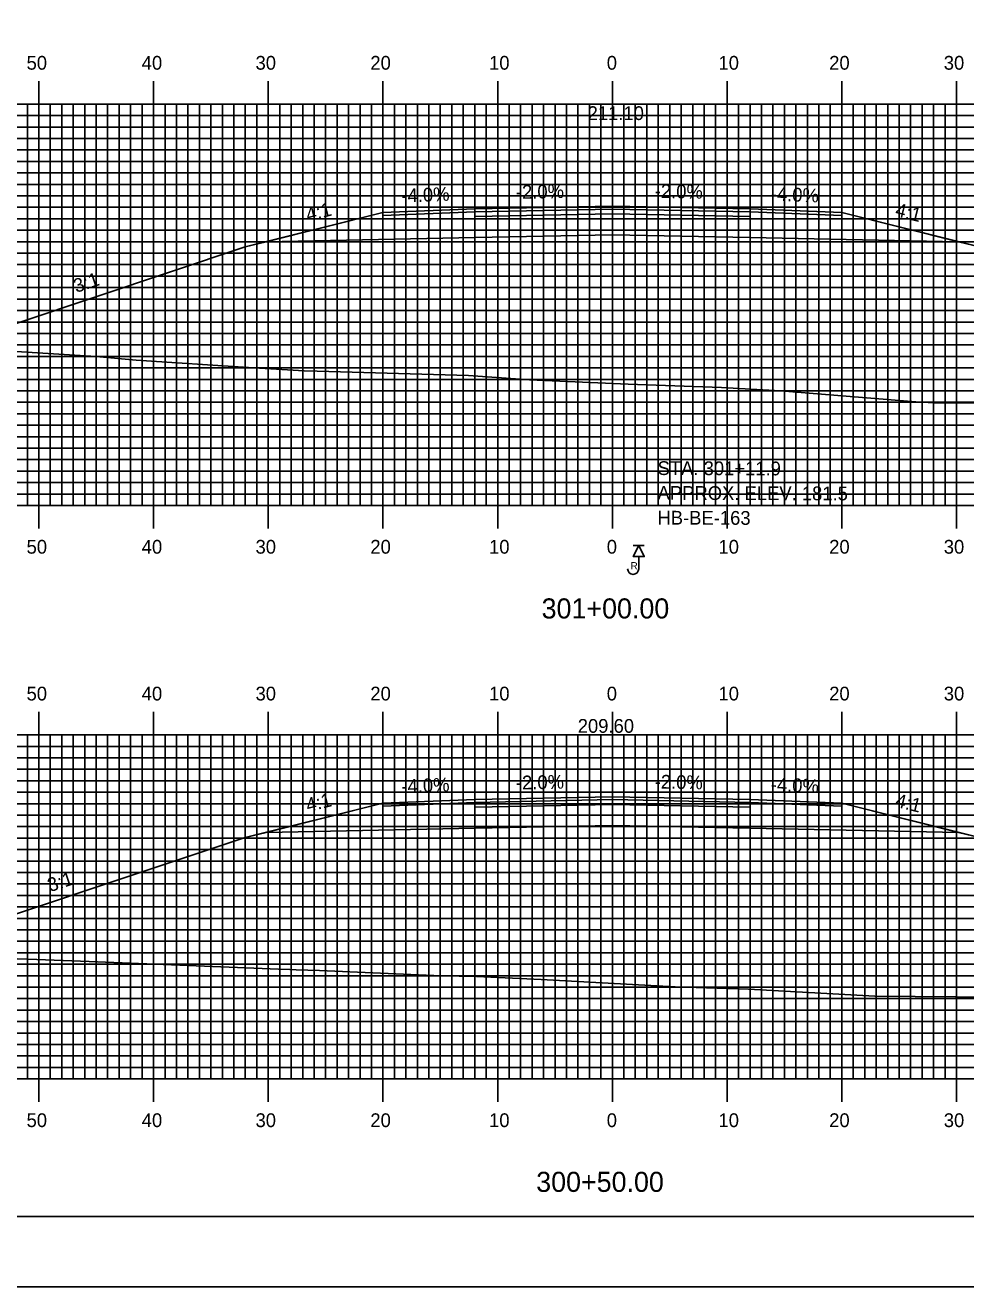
# Model space of a CAD drawing. Extents: x 1815702 to 1816046, y 442591 to 442811.
# Drawn here: x 1815816.9 to 1815898.9, y 442590.5 to 442700.5 of the extents above; entities that cross this region are included whole.
import ezdxf

# ---------------------------------------------------------------- set-up
doc = ezdxf.new("R2010")
doc.units = 0
for name, color, linetype in [('ANNOTATION', 7, 'Continuous'), ('BORDER', 7, 'Continuous'), ('BORING - REFUSAL', 7, 'Continuous'), ('D_Roadway_Centerline', 7, 'Continuous'), ('D_Roadway_Centerline_Text', 7, 'Continuous'), ('D_Roadway_Edge_Shoulder', 7, 'Continuous'), ('D_Roadway_Edge_TW', 7, 'Continuous'), ('D_Roadway_Pavement', 7, 'Continuous'), ('D_Roadway_SlopeLines', 7, 'Continuous'), ('D_Roadway_SubGrade', 7, 'Continuous'), ('H_V ANNOTATION', 7, 'Continuous'), ('MAJOR', 7, 'Continuous'), ('MINOR', 7, 'Continuous'), ('PLOT BOUNDARY', 7, 'Continuous'), ('S_Roadway_Centerline', 7, 'Continuous')]:
    doc.layers.add(name, color=color, linetype=linetype)

msp = doc.modelspace()

# ---------------------------------------------------------------- linework, layer by layer
at = {"layer": 'BORDER'}
msp.add_lwpolyline([(1815718.45, 442596.67), (1816038.45, 442596.67), (1816038.45, 442806.67), (1815718.45, 442806.67)], close=True, dxfattribs=at)
at = {"layer": 'BORING - REFUSAL'}
for p, q in [((1815870.83, 442655.17), (1815869.87, 442655.17)), ((1815870.35, 442654.21), (1815870.35, 442653.15))]:
    msp.add_line(p, q, dxfattribs=at)
msp.add_lwpolyline([(1815870.35, 442655.17), (1815870.83, 442654.21), (1815869.87, 442654.21)], close=True, dxfattribs=at)
msp.add_arc((1815869.86, 442653.15), 0.485, 180, 0, dxfattribs=at)
at = {"layer": 'D_Roadway_Centerline'}
for points in [[(1815809.89, 442672.49), (1815836.05, 442681.21), (1815837.87, 442681.67), (1815848.05, 442684.21), (1815856.05, 442684.53), (1815868.05, 442684.77), (1815880.05, 442684.53), (1815888.05, 442684.21), (1815898.22, 442681.67), (1815900.05, 442681.21), (1815945.68, 442666)], [(1815805.36, 442619.48), (1815836.05, 442629.71), (1815837.87, 442630.17), (1815848.05, 442632.71), (1815856.05, 442633.03), (1815868.05, 442633.27), (1815880.05, 442633.03), (1815888.05, 442632.71), (1815898.22, 442630.17), (1815900.05, 442629.71), (1815943, 442615.39)]]:
    msp.add_lwpolyline(points, dxfattribs=at)
at = {"layer": 'D_Roadway_Edge_Shoulder'}
for points in [[(1815856.05, 442684.53), (1815848.05, 442684.21), (1815848.05, 442683.96), (1815856.05, 442684.28)], [(1815880.05, 442684.53), (1815888.05, 442684.21), (1815888.05, 442683.96), (1815880.05, 442684.28)], [(1815856.05, 442633.03), (1815848.05, 442632.71), (1815848.05, 442632.46), (1815856.05, 442632.78)], [(1815880.05, 442633.03), (1815888.05, 442632.71), (1815888.05, 442632.46), (1815880.05, 442632.78)]]:
    msp.add_lwpolyline(points, close=True, dxfattribs=at)
at = {"layer": 'D_Roadway_Edge_TW'}
for points in [[(1815856.05, 442684.28), (1815856.05, 442684.53), (1815868.05, 442684.77), (1815880.05, 442684.53), (1815880.05, 442684.28), (1815868.05, 442684.52)], [(1815856.05, 442632.78), (1815856.05, 442633.03), (1815868.05, 442633.27), (1815880.05, 442633.03), (1815880.05, 442632.78), (1815868.05, 442633.02)]]:
    msp.add_lwpolyline(points, close=True, dxfattribs=at)
at = {"layer": 'D_Roadway_Pavement'}
for points in [[(1815856.05, 442683.86), (1815856.05, 442684.28), (1815868.05, 442684.52), (1815880.05, 442684.28), (1815880.05, 442683.86), (1815868.05, 442684.1)], [(1815856.05, 442632.36), (1815856.05, 442632.78), (1815868.05, 442633.02), (1815880.05, 442632.78), (1815880.05, 442632.36), (1815868.05, 442632.6)]]:
    msp.add_lwpolyline(points, close=True, dxfattribs=at)
at = {"layer": 'D_Roadway_SlopeLines'}
for points in [[(1815848.05, 442684.21), (1815836.05, 442681.21), (1815809.89, 442672.49)], [(1815888.05, 442684.21), (1815900.05, 442681.21), (1815945.68, 442666)], [(1815848.05, 442632.71), (1815836.05, 442629.71), (1815805.36, 442619.48)], [(1815888.05, 442632.71), (1815900.05, 442629.71), (1815943, 442615.39)]]:
    msp.add_lwpolyline(points, dxfattribs=at)
at = {"layer": 'D_Roadway_SubGrade'}
for points in [[(1815856.05, 442682.03), (1815837.87, 442681.67), (1815848.05, 442684.21), (1815848.05, 442683.96), (1815856.05, 442684.28), (1815868.05, 442684.52), (1815880.05, 442684.28), (1815888.05, 442683.96), (1815888.05, 442684.21), (1815898.22, 442681.67), (1815880.05, 442682.03), (1815868.05, 442682.27)], [(1815856.05, 442630.53), (1815837.87, 442630.17), (1815848.05, 442632.71), (1815848.05, 442632.46), (1815856.05, 442632.78), (1815868.05, 442633.02), (1815880.05, 442632.78), (1815888.05, 442632.46), (1815888.05, 442632.71), (1815898.22, 442630.17), (1815880.05, 442630.53), (1815868.05, 442630.77)]]:
    msp.add_lwpolyline(points, close=True, dxfattribs=at)
at = {"layer": 'MAJOR'}
for p, q in [((1815818.05, 442695.67), (1815818.05, 442693.67)), ((1815828.05, 442695.67), (1815828.05, 442693.67)), ((1815838.05, 442695.67), (1815838.05, 442693.67)), ((1815848.05, 442695.67), (1815848.05, 442693.67)), ((1815858.05, 442695.67), (1815858.05, 442693.67)), ((1815868.05, 442695.67), (1815868.05, 442693.67)), ((1815878.05, 442695.67), (1815878.05, 442693.67)), ((1815888.05, 442695.67), (1815888.05, 442693.67)), ((1815898.05, 442695.67), (1815898.05, 442693.67)), ((1815728.05, 442693.67), (1816008.05, 442693.67)), ((1815728.05, 442693.67), (1816008.05, 442693.67)), ((1815818.05, 442658.67), (1815818.05, 442693.67)), ((1815828.05, 442658.67), (1815828.05, 442693.67)), ((1815838.05, 442658.67), (1815838.05, 442693.67)), ((1815848.05, 442658.67), (1815848.05, 442693.67)), ((1815858.05, 442658.67), (1815858.05, 442693.67)), ((1815868.05, 442658.67), (1815868.05, 442693.67)), ((1815878.05, 442658.67), (1815878.05, 442693.67)), ((1815888.05, 442658.67), (1815888.05, 442693.67)), ((1815898.05, 442658.67), (1815898.05, 442693.67)), ((1815728.05, 442688.67), (1816008.05, 442688.67)), ((1815728.05, 442683.67), (1816008.05, 442683.67)), ((1815728.05, 442678.67), (1816008.05, 442678.67)), ((1815728.05, 442673.67), (1816008.05, 442673.67)), ((1815728.05, 442668.67), (1816008.05, 442668.67)), ((1815728.05, 442663.67), (1816008.05, 442663.67)), ((1815728.05, 442658.67), (1816008.05, 442658.67)), ((1815728.05, 442658.67), (1816008.05, 442658.67)), ((1815818.05, 442656.66), (1815818.05, 442658.67)), ((1815828.05, 442656.66), (1815828.05, 442658.67)), ((1815838.05, 442656.66), (1815838.05, 442658.67)), ((1815848.05, 442656.66), (1815848.05, 442658.67)), ((1815858.05, 442656.66), (1815858.05, 442658.67)), ((1815868.05, 442656.66), (1815868.05, 442658.67)), ((1815878.05, 442656.66), (1815878.05, 442658.67)), ((1815888.05, 442656.66), (1815888.05, 442658.67)), ((1815898.05, 442656.66), (1815898.05, 442658.67)), ((1815818.05, 442640.67), (1815818.05, 442638.67)), ((1815828.05, 442640.67), (1815828.05, 442638.67)), ((1815838.05, 442640.67), (1815838.05, 442638.67)), ((1815848.05, 442640.67), (1815848.05, 442638.67)), ((1815858.05, 442640.67), (1815858.05, 442638.67)), ((1815868.05, 442640.67), (1815868.05, 442638.67)), ((1815878.05, 442640.67), (1815878.05, 442638.67)), ((1815888.05, 442640.67), (1815888.05, 442638.67)), ((1815898.05, 442640.67), (1815898.05, 442638.67)), ((1815728.05, 442638.67), (1816008.05, 442638.67)), ((1815728.05, 442638.67), (1816008.05, 442638.67)), ((1815818.05, 442608.67), (1815818.05, 442638.67)), ((1815828.05, 442608.67), (1815828.05, 442638.67)), ((1815838.05, 442608.67), (1815838.05, 442638.67)), ((1815848.05, 442608.67), (1815848.05, 442638.67)), ((1815858.05, 442608.67), (1815858.05, 442638.67)), ((1815868.05, 442608.67), (1815868.05, 442638.67)), ((1815878.05, 442608.67), (1815878.05, 442638.67)), ((1815888.05, 442608.67), (1815888.05, 442638.67)), ((1815898.05, 442608.67), (1815898.05, 442638.67)), ((1815728.05, 442633.67), (1816008.05, 442633.67)), ((1815728.05, 442628.67), (1816008.05, 442628.67)), ((1815728.05, 442623.67), (1816008.05, 442623.67)), ((1815728.05, 442618.67), (1816008.05, 442618.67)), ((1815728.05, 442613.67), (1816008.05, 442613.67)), ((1815728.05, 442608.67), (1816008.05, 442608.67)), ((1815728.05, 442608.67), (1816008.05, 442608.67)), ((1815818.05, 442606.66), (1815818.05, 442608.67)), ((1815828.05, 442606.66), (1815828.05, 442608.67)), ((1815838.05, 442606.66), (1815838.05, 442608.67)), ((1815848.05, 442606.66), (1815848.05, 442608.67)), ((1815858.05, 442606.66), (1815858.05, 442608.67)), ((1815868.05, 442606.66), (1815868.05, 442608.67)), ((1815878.05, 442606.66), (1815878.05, 442608.67)), ((1815888.05, 442606.66), (1815888.05, 442608.67)), ((1815898.05, 442606.66), (1815898.05, 442608.67))]:
    msp.add_line(p, q, dxfattribs=at)
at = {"layer": 'MINOR'}
for p, q in [((1815817.05, 442658.67), (1815817.05, 442693.67)), ((1815819.05, 442658.67), (1815819.05, 442693.67)), ((1815820.05, 442658.67), (1815820.05, 442693.67)), ((1815821.05, 442658.67), (1815821.05, 442693.67)), ((1815822.05, 442658.67), (1815822.05, 442693.67)), ((1815823.05, 442658.67), (1815823.05, 442693.67)), ((1815824.05, 442658.67), (1815824.05, 442693.67)), ((1815825.05, 442658.67), (1815825.05, 442693.67)), ((1815826.05, 442658.67), (1815826.05, 442693.67)), ((1815827.05, 442658.67), (1815827.05, 442693.67)), ((1815829.05, 442658.67), (1815829.05, 442693.67)), ((1815830.05, 442658.67), (1815830.05, 442693.67)), ((1815831.05, 442658.67), (1815831.05, 442693.67)), ((1815832.05, 442658.67), (1815832.05, 442693.67)), ((1815833.05, 442658.67), (1815833.05, 442693.67)), ((1815834.05, 442658.67), (1815834.05, 442693.67)), ((1815835.05, 442658.67), (1815835.05, 442693.67)), ((1815836.05, 442658.67), (1815836.05, 442693.67)), ((1815837.05, 442658.67), (1815837.05, 442693.67)), ((1815839.05, 442658.67), (1815839.05, 442693.67)), ((1815840.05, 442658.67), (1815840.05, 442693.67)), ((1815841.05, 442658.67), (1815841.05, 442693.67)), ((1815842.05, 442658.67), (1815842.05, 442693.67)), ((1815843.05, 442658.67), (1815843.05, 442693.67)), ((1815844.05, 442658.67), (1815844.05, 442693.67)), ((1815845.05, 442658.67), (1815845.05, 442693.67)), ((1815846.05, 442658.67), (1815846.05, 442693.67)), ((1815847.05, 442658.67), (1815847.05, 442693.67)), ((1815849.05, 442658.67), (1815849.05, 442693.67)), ((1815850.05, 442658.67), (1815850.05, 442693.67)), ((1815851.05, 442658.67), (1815851.05, 442693.67)), ((1815852.05, 442658.67), (1815852.05, 442693.67)), ((1815853.05, 442658.67), (1815853.05, 442693.67)), ((1815854.05, 442658.67), (1815854.05, 442693.67)), ((1815855.05, 442658.67), (1815855.05, 442693.67)), ((1815856.05, 442658.67), (1815856.05, 442693.67)), ((1815857.05, 442658.67), (1815857.05, 442693.67)), ((1815859.05, 442658.67), (1815859.05, 442693.67)), ((1815860.05, 442658.67), (1815860.05, 442693.67)), ((1815861.05, 442658.67), (1815861.05, 442693.67)), ((1815862.05, 442658.67), (1815862.05, 442693.67)), ((1815863.05, 442658.67), (1815863.05, 442693.67)), ((1815864.05, 442658.67), (1815864.05, 442693.67)), ((1815865.05, 442658.67), (1815865.05, 442693.67)), ((1815866.05, 442658.67), (1815866.05, 442693.67)), ((1815867.05, 442658.67), (1815867.05, 442693.67)), ((1815869.05, 442658.67), (1815869.05, 442693.67)), ((1815870.05, 442658.67), (1815870.05, 442693.67)), ((1815871.05, 442658.67), (1815871.05, 442693.67)), ((1815872.05, 442658.67), (1815872.05, 442693.67)), ((1815873.05, 442658.67), (1815873.05, 442693.67)), ((1815874.05, 442658.67), (1815874.05, 442693.67)), ((1815875.05, 442658.67), (1815875.05, 442693.67)), ((1815876.05, 442658.67), (1815876.05, 442693.67)), ((1815877.05, 442658.67), (1815877.05, 442693.67)), ((1815879.05, 442658.67), (1815879.05, 442693.67)), ((1815880.05, 442658.67), (1815880.05, 442693.67)), ((1815881.05, 442658.67), (1815881.05, 442693.67)), ((1815882.05, 442658.67), (1815882.05, 442693.67)), ((1815883.05, 442658.67), (1815883.05, 442693.67)), ((1815884.05, 442658.67), (1815884.05, 442693.67)), ((1815885.05, 442658.67), (1815885.05, 442693.67)), ((1815886.05, 442658.67), (1815886.05, 442693.67)), ((1815887.05, 442658.67), (1815887.05, 442693.67)), ((1815889.05, 442658.67), (1815889.05, 442693.67)), ((1815890.05, 442658.67), (1815890.05, 442693.67)), ((1815891.05, 442658.67), (1815891.05, 442693.67)), ((1815892.05, 442658.67), (1815892.05, 442693.67)), ((1815893.05, 442658.67), (1815893.05, 442693.67)), ((1815894.05, 442658.67), (1815894.05, 442693.67)), ((1815895.05, 442658.67), (1815895.05, 442693.67)), ((1815896.05, 442658.67), (1815896.05, 442693.67)), ((1815897.05, 442658.67), (1815897.05, 442693.67)), ((1815728.05, 442692.67), (1816008.05, 442692.67)), ((1815728.05, 442691.67), (1816008.05, 442691.67)), ((1815728.05, 442690.67), (1816008.05, 442690.67)), ((1815728.05, 442689.67), (1816008.05, 442689.67)), ((1815728.05, 442687.67), (1816008.05, 442687.67)), ((1815728.05, 442686.67), (1816008.05, 442686.67)), ((1815728.05, 442685.67), (1816008.05, 442685.67)), ((1815728.05, 442684.67), (1816008.05, 442684.67)), ((1815728.05, 442682.67), (1816008.05, 442682.67)), ((1815728.05, 442681.67), (1816008.05, 442681.67)), ((1815728.05, 442680.67), (1816008.05, 442680.67)), ((1815728.05, 442679.67), (1816008.05, 442679.67)), ((1815728.05, 442677.67), (1816008.05, 442677.67)), ((1815728.05, 442676.67), (1816008.05, 442676.67)), ((1815728.05, 442675.67), (1816008.05, 442675.67)), ((1815728.05, 442674.67), (1816008.05, 442674.67)), ((1815728.05, 442672.67), (1816008.05, 442672.67)), ((1815728.05, 442671.67), (1816008.05, 442671.67)), ((1815728.05, 442670.67), (1816008.05, 442670.67)), ((1815728.05, 442669.67), (1816008.05, 442669.67)), ((1815728.05, 442667.67), (1816008.05, 442667.67)), ((1815728.05, 442666.67), (1816008.05, 442666.67)), ((1815728.05, 442665.67), (1816008.05, 442665.67)), ((1815728.05, 442664.67), (1816008.05, 442664.67)), ((1815728.05, 442662.67), (1816008.05, 442662.67)), ((1815728.05, 442661.67), (1816008.05, 442661.67)), ((1815728.05, 442660.67), (1816008.05, 442660.67)), ((1815728.05, 442659.67), (1816008.05, 442659.67)), ((1815817.05, 442608.67), (1815817.05, 442638.67)), ((1815819.05, 442608.67), (1815819.05, 442638.67)), ((1815820.05, 442608.67), (1815820.05, 442638.67)), ((1815821.05, 442608.67), (1815821.05, 442638.67)), ((1815822.05, 442608.67), (1815822.05, 442638.67)), ((1815823.05, 442608.67), (1815823.05, 442638.67)), ((1815824.05, 442608.67), (1815824.05, 442638.67)), ((1815825.05, 442608.67), (1815825.05, 442638.67)), ((1815826.05, 442608.67), (1815826.05, 442638.67)), ((1815827.05, 442608.67), (1815827.05, 442638.67)), ((1815829.05, 442608.67), (1815829.05, 442638.67)), ((1815830.05, 442608.67), (1815830.05, 442638.67)), ((1815831.05, 442608.67), (1815831.05, 442638.67)), ((1815832.05, 442608.67), (1815832.05, 442638.67)), ((1815833.05, 442608.67), (1815833.05, 442638.67)), ((1815834.05, 442608.67), (1815834.05, 442638.67)), ((1815835.05, 442608.67), (1815835.05, 442638.67)), ((1815836.05, 442608.67), (1815836.05, 442638.67)), ((1815837.05, 442608.67), (1815837.05, 442638.67)), ((1815839.05, 442608.67), (1815839.05, 442638.67)), ((1815840.05, 442608.67), (1815840.05, 442638.67)), ((1815841.05, 442608.67), (1815841.05, 442638.67)), ((1815842.05, 442608.67), (1815842.05, 442638.67)), ((1815843.05, 442608.67), (1815843.05, 442638.67)), ((1815844.05, 442608.67), (1815844.05, 442638.67)), ((1815845.05, 442608.67), (1815845.05, 442638.67)), ((1815846.05, 442608.67), (1815846.05, 442638.67)), ((1815847.05, 442608.67), (1815847.05, 442638.67)), ((1815849.05, 442608.67), (1815849.05, 442638.67)), ((1815850.05, 442608.67), (1815850.05, 442638.67)), ((1815851.05, 442608.67), (1815851.05, 442638.67)), ((1815852.05, 442608.67), (1815852.05, 442638.67)), ((1815853.05, 442608.67), (1815853.05, 442638.67)), ((1815854.05, 442608.67), (1815854.05, 442638.67)), ((1815855.05, 442608.67), (1815855.05, 442638.67)), ((1815856.05, 442608.67), (1815856.05, 442638.67)), ((1815857.05, 442608.67), (1815857.05, 442638.67)), ((1815859.05, 442608.67), (1815859.05, 442638.67)), ((1815860.05, 442608.67), (1815860.05, 442638.67)), ((1815861.05, 442608.67), (1815861.05, 442638.67)), ((1815862.05, 442608.67), (1815862.05, 442638.67)), ((1815863.05, 442608.67), (1815863.05, 442638.67)), ((1815864.05, 442608.67), (1815864.05, 442638.67)), ((1815865.05, 442608.67), (1815865.05, 442638.67)), ((1815866.05, 442608.67), (1815866.05, 442638.67)), ((1815867.05, 442608.67), (1815867.05, 442638.67)), ((1815869.05, 442608.67), (1815869.05, 442638.67)), ((1815870.05, 442608.67), (1815870.05, 442638.67)), ((1815871.05, 442608.67), (1815871.05, 442638.67)), ((1815872.05, 442608.67), (1815872.05, 442638.67)), ((1815873.05, 442608.67), (1815873.05, 442638.67)), ((1815874.05, 442608.67), (1815874.05, 442638.67)), ((1815875.05, 442608.67), (1815875.05, 442638.67)), ((1815876.05, 442608.67), (1815876.05, 442638.67)), ((1815877.05, 442608.67), (1815877.05, 442638.67)), ((1815879.05, 442608.67), (1815879.05, 442638.67)), ((1815880.05, 442608.67), (1815880.05, 442638.67)), ((1815881.05, 442608.67), (1815881.05, 442638.67)), ((1815882.05, 442608.67), (1815882.05, 442638.67)), ((1815883.05, 442608.67), (1815883.05, 442638.67)), ((1815884.05, 442608.67), (1815884.05, 442638.67)), ((1815885.05, 442608.67), (1815885.05, 442638.67)), ((1815886.05, 442608.67), (1815886.05, 442638.67)), ((1815887.05, 442608.67), (1815887.05, 442638.67)), ((1815889.05, 442608.67), (1815889.05, 442638.67)), ((1815890.05, 442608.67), (1815890.05, 442638.67)), ((1815891.05, 442608.67), (1815891.05, 442638.67)), ((1815892.05, 442608.67), (1815892.05, 442638.67)), ((1815893.05, 442608.67), (1815893.05, 442638.67)), ((1815894.05, 442608.67), (1815894.05, 442638.67)), ((1815895.05, 442608.67), (1815895.05, 442638.67)), ((1815896.05, 442608.67), (1815896.05, 442638.67)), ((1815897.05, 442608.67), (1815897.05, 442638.67)), ((1815728.05, 442637.67), (1816008.05, 442637.67)), ((1815728.05, 442636.67), (1816008.05, 442636.67)), ((1815728.05, 442635.67), (1816008.05, 442635.67)), ((1815728.05, 442634.67), (1816008.05, 442634.67)), ((1815728.05, 442632.67), (1816008.05, 442632.67)), ((1815728.05, 442631.67), (1816008.05, 442631.67)), ((1815728.05, 442630.67), (1816008.05, 442630.67)), ((1815728.05, 442629.67), (1816008.05, 442629.67)), ((1815728.05, 442627.67), (1816008.05, 442627.67)), ((1815728.05, 442626.67), (1816008.05, 442626.67)), ((1815728.05, 442625.67), (1816008.05, 442625.67)), ((1815728.05, 442624.67), (1816008.05, 442624.67)), ((1815728.05, 442622.67), (1816008.05, 442622.67)), ((1815728.05, 442621.67), (1816008.05, 442621.67)), ((1815728.05, 442620.67), (1816008.05, 442620.67)), ((1815728.05, 442619.67), (1816008.05, 442619.67)), ((1815728.05, 442617.67), (1816008.05, 442617.67)), ((1815728.05, 442616.67), (1816008.05, 442616.67)), ((1815728.05, 442615.67), (1816008.05, 442615.67)), ((1815728.05, 442614.67), (1816008.05, 442614.67)), ((1815728.05, 442612.67), (1816008.05, 442612.67)), ((1815728.05, 442611.67), (1816008.05, 442611.67)), ((1815728.05, 442610.67), (1816008.05, 442610.67)), ((1815728.05, 442609.67), (1816008.05, 442609.67))]:
    msp.add_line(p, q, dxfattribs=at)
at = {"layer": 'PLOT BOUNDARY'}
msp.add_lwpolyline([(1815702.26, 442590.55), (1816042.26, 442590.55), (1816042.26, 442810.55), (1815702.26, 442810.55)], close=True, dxfattribs=at)
at = {"layer": 'S_Roadway_Centerline'}
for points in [[(1815809.56, 442672.51), (1815823.05, 442671.65), (1815826.54, 442671.35), (1815836.32, 442670.69), (1815841.18, 442670.41), (1815842.31, 442670.37), (1815855.5, 442670.01), (1815860.83, 442669.64), (1815869.42, 442669.24), (1815877.56, 442668.97), (1815882.7, 442668.66), (1815894.49, 442667.72), (1815896.09, 442667.63), (1815900.12, 442667.6), (1815912.51, 442667.31), (1815923.93, 442666.7), (1815928.95, 442666.66), (1815937.45, 442666.3), (1815948.91, 442665.88), (1815962.14, 442665.79), (1815970.07, 442665.5), (1815986.57, 442665.4), (1816007.47, 442665.13), (1816008.05, 442665.13)], [(1815805.51, 442619.47), (1815817.11, 442619.1), (1815822.45, 442618.9), (1815838.94, 442618.25), (1815839.92, 442618.22), (1815840.49, 442618.19), (1815842.51, 442618.11), (1815853.16, 442617.67), (1815856.2, 442617.59), (1815861.83, 442617.35), (1815873.52, 442616.69), (1815879.92, 442616.49), (1815890.93, 442615.88), (1815904.99, 442615.76), (1815907.15, 442615.75), (1815907.54, 442615.75), (1815908.18, 442615.73), (1815924.18, 442615.54), (1815931.51, 442615.58), (1815941.78, 442615.41), (1815966.62, 442615.08)]]:
    msp.add_lwpolyline(points, dxfattribs=at)

# ---------------------------------------------------------------- texts
at = {"layer": 'ANNOTATION'}
for s, rotation, p in [('-4.0%', 2.2906, (1815849.68, 442685.08)), ('-2.0%', 1.1458, (1815859.65, 442685.4)), ('-2.0%', 358.8542, (1815871.73, 442685.5)), ('-4.0%', 357.7094, (1815881.84, 442685.26)), ('4:1', 14.0362, (1815841.5, 442683.43)), ('4:1', 345.9638, (1815892.64, 442683.92)), ('3:1', 18.4348, (1815821.31, 442677.2)), ('-4.0%', 2.2906, (1815849.68, 442633.58)), ('-2.0%', 1.1458, (1815859.65, 442633.9)), ('-2.0%', 358.8542, (1815871.73, 442634)), ('-4.0%', 357.7094, (1815881.84, 442633.76)), ('4:1', 14.0362, (1815841.5, 442631.93)), ('4:1', 345.9638, (1815892.64, 442632.42)), ('3:1', 18.4348, (1815819.04, 442624.95))]:
    msp.add_text(s, height=1.2, rotation=rotation, dxfattribs=at).set_placement(p)
at = {"layer": 'BORING - REFUSAL'}
for s, p in [('STA. 301+11.9', (1815871.99, 442661.33)), ('APPROX. ELEV. 181.5', (1815871.99, 442659.17)), ('HB-BE-163', (1815871.98, 442657.01))]:
    msp.add_text(s, height=1.2, rotation=359.8142, dxfattribs=at).set_placement(p)
msp.add_text('R', height=0.64, dxfattribs=at).set_placement((1815869.64, 442653.09))
at = {"layer": 'D_Roadway_Centerline'}
for s, p in [('C', (1815868.04, 442684.77)), ('L', (1815868.05, 442684.76)), ('C', (1815868.04, 442633.27)), ('L', (1815868.05, 442633.26))]:
    msp.add_text(s, height=0.0146, dxfattribs=at).set_placement(p)
at = {"layer": 'D_Roadway_Centerline_Text'}
for s, p in [('211.10', (1815865.89, 442692.28)), ('209.60', (1815865.03, 442638.85))]:
    msp.add_text(s, height=1.2, dxfattribs=at).set_placement(p)
at = {"layer": 'H_V ANNOTATION'}
for s, height, p in [('50', 1.2, (1815816.98, 442696.67)), ('40', 1.2, (1815827.02, 442696.67)), ('30', 1.2, (1815836.94, 442696.67)), ('20', 1.2, (1815846.95, 442696.67)), ('10', 1.2, (1815857.3, 442696.67)), ('0', 1.2, (1815867.56, 442696.67)), ('10', 1.2, (1815877.3, 442696.67)), ('20', 1.2, (1815886.95, 442696.67)), ('30', 1.2, (1815896.94, 442696.67)), ('50', 1.2, (1815816.98, 442654.47)), ('40', 1.2, (1815827.02, 442654.47)), ('30', 1.2, (1815836.94, 442654.47)), ('20', 1.2, (1815846.95, 442654.47)), ('10', 1.2, (1815857.3, 442654.47)), ('0', 1.2, (1815867.56, 442654.47)), ('10', 1.2, (1815877.3, 442654.47)), ('20', 1.2, (1815886.95, 442654.47)), ('30', 1.2, (1815896.94, 442654.47)), ('301+00.00', 1.75, (1815861.88, 442648.82)), ('50', 1.2, (1815816.98, 442641.67)), ('40', 1.2, (1815827.02, 442641.67)), ('30', 1.2, (1815836.94, 442641.67)), ('20', 1.2, (1815846.95, 442641.67)), ('10', 1.2, (1815857.3, 442641.67)), ('0', 1.2, (1815867.56, 442641.67)), ('10', 1.2, (1815877.3, 442641.67)), ('20', 1.2, (1815886.95, 442641.67)), ('30', 1.2, (1815896.94, 442641.67)), ('50', 1.2, (1815816.98, 442604.47)), ('40', 1.2, (1815827.02, 442604.47)), ('30', 1.2, (1815836.94, 442604.47)), ('20', 1.2, (1815846.95, 442604.47)), ('10', 1.2, (1815857.3, 442604.47)), ('0', 1.2, (1815867.56, 442604.47)), ('10', 1.2, (1815877.3, 442604.47)), ('20', 1.2, (1815886.95, 442604.47)), ('30', 1.2, (1815896.94, 442604.47)), ('300+50.00', 1.75, (1815861.41, 442598.82))]:
    msp.add_text(s, height=height, dxfattribs=at).set_placement(p)

doc.saveas('drawing.dxf')
